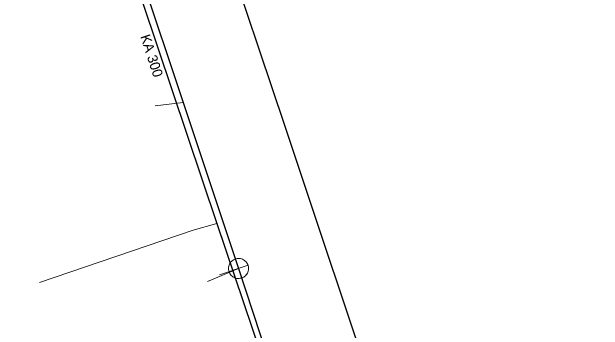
# Model space of a CAD drawing. Extents: x -807203 to -805207, y -993656 to -992505.
# Drawn here: x -807085.4 to -807026.3, y -993257 to -993225.3 of the extents above; entities that cross this region are included whole.
import ezdxf

# ---------------------------------------------------------------- set-up
doc = ezdxf.new("R2010")
doc.units = 0
doc.header["$LTSCALE"] = 0.4
for name, color, linetype, lineweight in [('1', 7, 'Continuous', 13), ('11', 7, 'Continuous', 13), ('13', 7, 'Continuous', 13), ('14', 7, 'Continuous', 25), ('17', 7, 'Continuous', 25), ('22', 7, 'Continuous', 13)]:
    doc.layers.add(name, color=color, linetype=linetype, lineweight=lineweight)

msp = doc.modelspace()

# ---------------------------------------------------------------- linework, layer by layer
at = {"layer": '11'}
for p, q in [((-807071.067, -993234.659), (-807068.265, -993234.297)), ((-807065.832, -993252.166), (-807062.73, -993250.879))]:
    msp.add_line(p, q, dxfattribs=at)
at = {"layer": '13'}
msp.add_lwpolyline([(-807064.891, -993246.39), (-807067.279, -993247.069), (-807082.628, -993252.298)], dxfattribs=at)
at = {"layer": '14'}
for points in [[(-807076.719, -993208.969), (-807068.265, -993234.297), (-807062.73, -993250.879)], [(-807062.73, -993250.879), (-807059.881, -993259.594), (-807051.68, -993284.69)]]:
    msp.add_lwpolyline(points, dxfattribs=at)
at = {"layer": '17'}
for points in [[(-807102.744, -993101.5), (-807102.241, -993103.247), (-807100.675, -993108.116), (-807100.243, -993109.059), (-807099.234, -993112.603), (-807098.39, -993115.482), (-807094.98, -993125.833), (-807093.653, -993129.923), (-807088.842, -993144.708), (-807087.517, -993148.8), (-807087.074, -993150.114), (-807085.368, -993155.225), (-807083.942, -993159.686), (-807072.827, -993193.081), (-807070.855, -993198.727), (-807058.136, -993236.557), (-807055.798, -993243.556), (-807050.671, -993258.89), (-807046.204, -993272.388), (-807040.605, -993289.576), (-807026.284, -993334.262)], [(-807106.216, -993120.722), (-807103.627, -993128.16), (-807102.219, -993132), (-807096.589, -993150.385), (-807096.195, -993151.629), (-807092.921, -993162.153), (-807079.791, -993202.059), (-807064.89, -993246.39), (-807059.596, -993262.052), (-807055.035, -993275.397), (-807053.806, -993278.989)]]:
    msp.add_lwpolyline(points, dxfattribs=at)
at = {"layer": '22'}
msp.add_line((-807064.627, -993251.512), (-807061.781, -993250.562), dxfattribs=at)
msp.add_lwpolyline([(-807062.413, -993251.827), (-807062.312, -993251.787), (-807062.215, -993251.736), (-807062.124, -993251.674), (-807062.041, -993251.604), (-807061.965, -993251.524), (-807061.9, -993251.436), (-807061.844, -993251.342), (-807061.799, -993251.243), (-807061.764, -993251.138), (-807061.742, -993251.032), (-807061.731, -993250.922), (-807061.733, -993250.812), (-807061.746, -993250.704), (-807061.771, -993250.597), (-807061.807, -993250.494), (-807061.855, -993250.396), (-807061.912, -993250.302), (-807061.98, -993250.216), (-807062.058, -993250.139), (-807062.142, -993250.07), (-807062.235, -993250.01), (-807062.332, -993249.961), (-807062.435, -993249.923), (-807062.541, -993249.896), (-807062.649, -993249.882), (-807062.759, -993249.879), (-807062.869, -993249.889), (-807062.975, -993249.91), (-807063.08, -993249.942), (-807063.181, -993249.986), (-807063.276, -993250.04), (-807063.363, -993250.105), (-807063.444, -993250.179), (-807063.517, -993250.261), (-807063.58, -993250.352), (-807063.632, -993250.447), (-807063.674, -993250.549), (-807063.704, -993250.654), (-807063.723, -993250.761), (-807063.73, -993250.871), (-807063.725, -993250.98), (-807063.708, -993251.088), (-807063.679, -993251.194), (-807063.639, -993251.296), (-807063.587, -993251.393), (-807063.527, -993251.483), (-807063.455, -993251.567), (-807063.375, -993251.642), (-807063.288, -993251.708), (-807063.194, -993251.764), (-807063.095, -993251.81), (-807062.991, -993251.844), (-807062.884, -993251.867), (-807062.775, -993251.877), (-807062.666, -993251.877), (-807062.556, -993251.863), (-807062.45, -993251.838)], close=True, dxfattribs=at)

# ---------------------------------------------------------------- texts
at = {"layer": '1'}
msp.add_text('KA 300', height=1, rotation=288, dxfattribs=at).set_placement((-807072.557, -993227.707))

doc.saveas('drawing.dxf')
